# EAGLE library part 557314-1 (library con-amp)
AMP connector
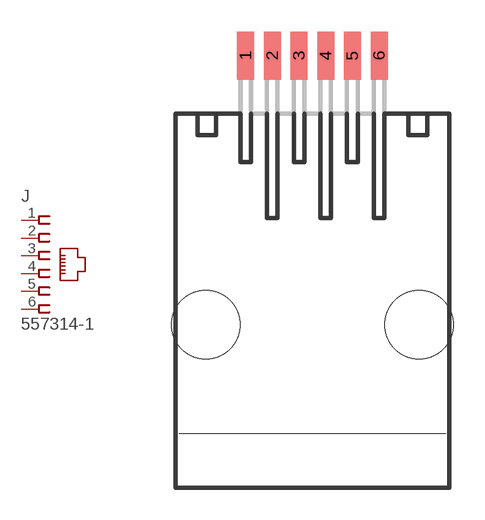
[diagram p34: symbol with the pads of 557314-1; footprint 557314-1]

Designator prefix J

## 557314-1 (MF: TYCO ELECTRONICS; MPN: 5557314-1; OC_FARNELL: 1522225; OC_NEWARK: 42K7304)  [557314-1]
1  1  pas
2  2  pas
3  3  pas
4  4  pas
5  5  pas
6  6  pas

## Footprint 557314-1 (pad centres in mm)
Modular Jack without Panel Stops
smd 0.813 x 2.286: 1 -3.175,12.803; 2 -1.905,12.803; 3 -0.635,12.803; 4 0.635,12.803; 5 1.905,12.803; 6 3.175,12.803
hole 3.251 at -5.08,0
hole 3.251 at 5.08,0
